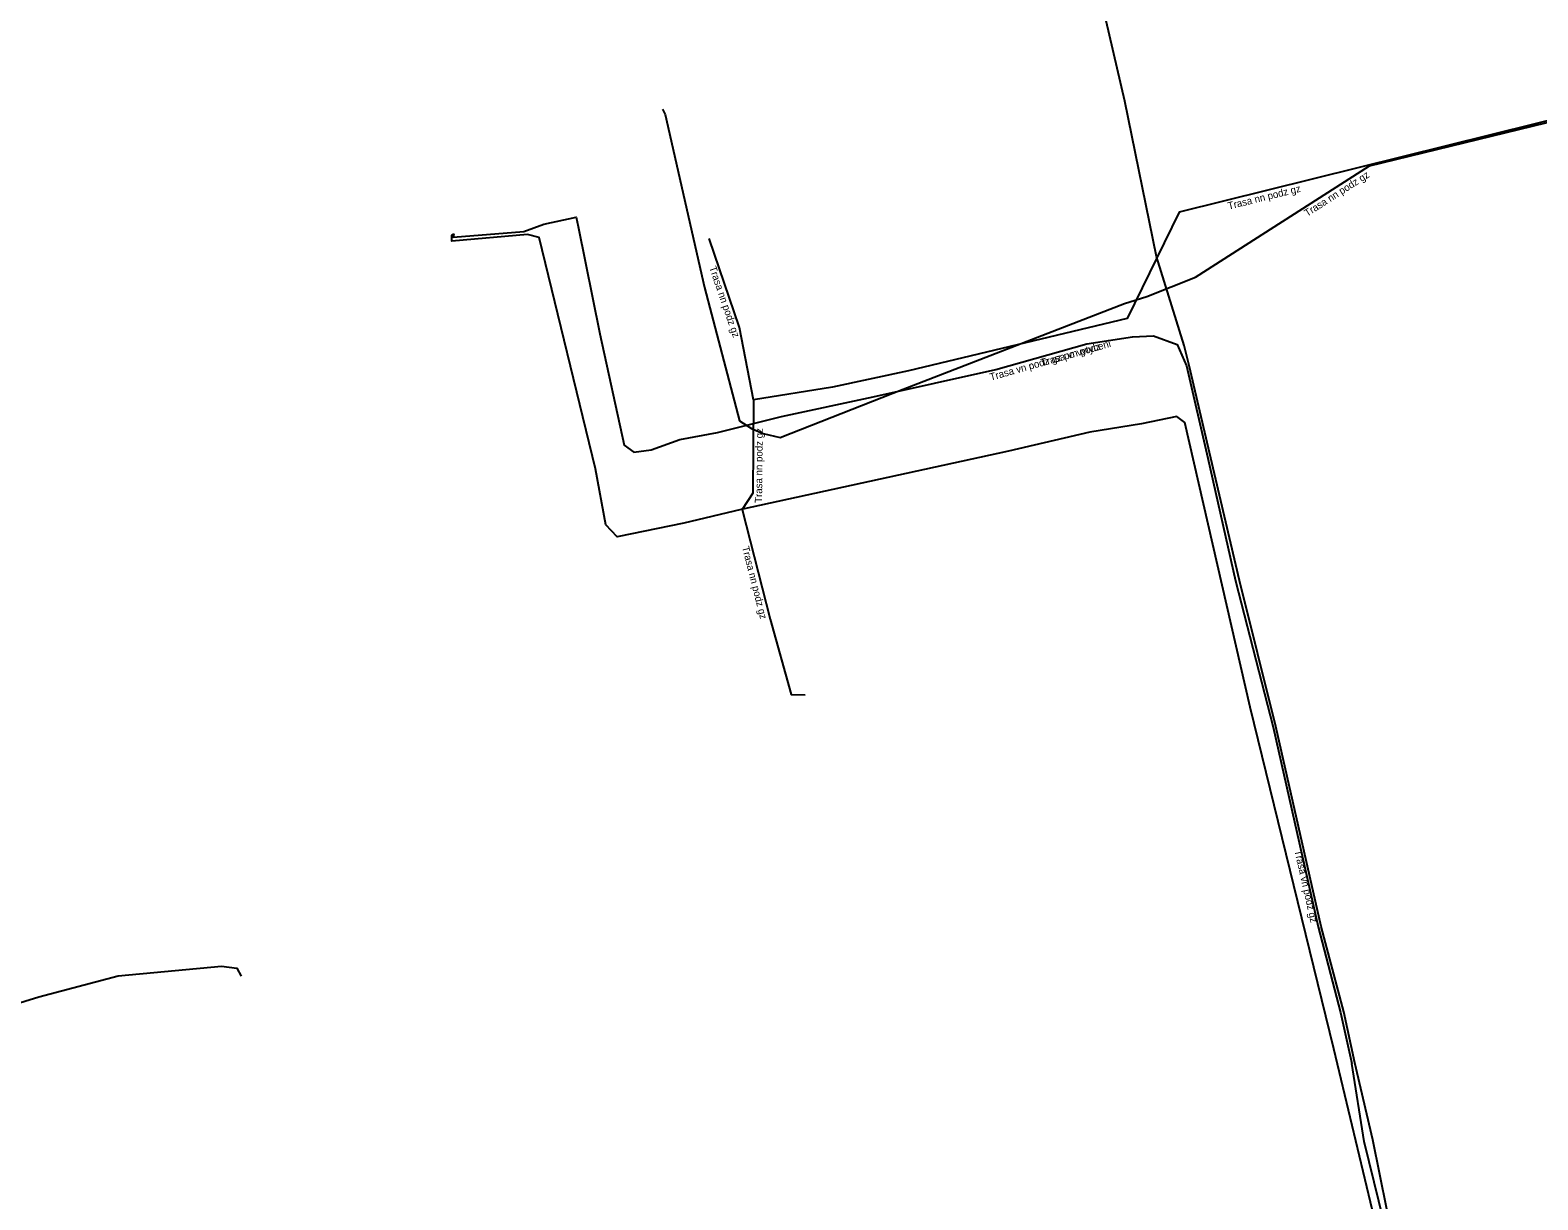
# Model space of a CAD drawing. Extents: x -473082 to -472599, y -1107914 to -1107370.
# Drawn here: x -472981 to -472876.8, y -1107632.7 to -1107551.9 of the extents above; entities that cross this region are included whole.
import ezdxf

# ---------------------------------------------------------------- set-up
doc = ezdxf.new("R2010")
doc.units = 0
for name, color, linetype in [('Popiskový text - Ostatní atributy Trasy', 7, 'Continuous'), ('Spojnice NN', 7, 'Continuous'), ('Spojnice VN', 7, 'Continuous')]:
    doc.layers.add(name, color=color, linetype=linetype)

msp = doc.modelspace()

# ---------------------------------------------------------------- linework, layer by layer
at = {"layer": 'Spojnice NN'}
for points in [[(-472853.99, -1107552.31), (-472861.54, -1107554.54), (-472901.55, -1107564.47), (-472905.15, -1107571.8), (-472913.81, -1107573.89), (-472920.25, -1107575.42), (-472925.51, -1107576.56), (-472930.96, -1107577.42)], [(-472937.26, -1107557.34), (-472937.08, -1107557.71), (-472934.36, -1107569.66), (-472931.94, -1107578.87), (-472931.11, -1107579.4), (-472930.3, -1107579.76), (-472929.13, -1107580.04), (-472921.35, -1107576.98), (-472905.33, -1107570.78), (-472903.79, -1107570.29), (-472900.43, -1107568.96), (-472888.4, -1107561.26), (-472867.72, -1107556.23)], [(-472930.96, -1107577.42), (-472931.93, -1107572.44), (-472934.04, -1107566.29)], [(-472930.96, -1107577.42), (-472931.02, -1107583.88)], [(-472931.02, -1107583.88), (-472931.76, -1107585.01), (-472929.83, -1107592.59), (-472928.36, -1107597.79), (-472927.41, -1107597.8)], [(-472981.13, -1107637.11), (-472982.76, -1107629.43), (-472984.24, -1107619.86), (-472980.36, -1107618.68), (-472974.86, -1107617.23), (-472967.73, -1107616.56), (-472966.66, -1107616.69), (-472966.37, -1107617.24)]]:
    msp.add_lwpolyline(points, dxfattribs=at)
at = {"layer": 'Spojnice VN'}
for points in [[(-472875.95, -1107634.94), (-472882.42, -1107637.24), (-472884.7, -1107637.44), (-472886.06, -1107636.68), (-472886.73, -1107635.73), (-472888.17, -1107628.55), (-472889.42, -1107623.23), (-472890.17, -1107619.72), (-472891.75, -1107613.81), (-472894.87, -1107599.99), (-472897.4, -1107589.9), (-472899.37, -1107581.45), (-472900.86, -1107575.05), (-472901.22, -1107573.68), (-472903.13, -1107567.52), (-472905.32, -1107556.79), (-472907.67, -1107546.67)], [(-472951.68, -1107565.97), (-472951.73, -1107566.19), (-472946.84, -1107565.81), (-472945.46, -1107565.29), (-472943.22, -1107564.81), (-472943.09, -1107565.46), (-472941.6, -1107572.87), (-472939.91, -1107580.56), (-472939.25, -1107581.04), (-472938.05, -1107580.89), (-472936.06, -1107580.17), (-472933.46, -1107579.69), (-472929.03, -1107578.59), (-472922.71, -1107577.22), (-472914.23, -1107575.34), (-472907.93, -1107573.56), (-472904.79, -1107573.07), (-472903.32, -1107573.02), (-472901.69, -1107573.61), (-472901.04, -1107575.09), (-472899.57, -1107581.47), (-472897.66, -1107589.93), (-472895.07, -1107600.05), (-472891.96, -1107613.84), (-472890.4, -1107619.76), (-472889.63, -1107623.29)], [(-472951.68, -1107565.97), (-472951.73, -1107566.19), (-472946.84, -1107565.81), (-472945.46, -1107565.29), (-472943.22, -1107564.81), (-472943.09, -1107565.46), (-472941.6, -1107572.87), (-472939.91, -1107580.56), (-472939.25, -1107581.04), (-472938.05, -1107580.89), (-472936.06, -1107580.17), (-472933.46, -1107579.69), (-472929.03, -1107578.59), (-472922.71, -1107577.22), (-472914.23, -1107575.34), (-472907.93, -1107573.56), (-472904.79, -1107573.07), (-472903.32, -1107573.02), (-472901.69, -1107573.61), (-472901.04, -1107575.09), (-472899.57, -1107581.47), (-472897.66, -1107589.93), (-472895.07, -1107600.05), (-472891.96, -1107613.84), (-472890.4, -1107619.76), (-472889.63, -1107623.29)], [(-472872.74, -1107635.74), (-472879.7, -1107636.72), (-472885.57, -1107637.54), (-472886.75, -1107637.43), (-472887.57, -1107636.03), (-472890.88, -1107622.26), (-472896.66, -1107598.66), (-472901.17, -1107578.99), (-472901.72, -1107578.58), (-472904.16, -1107579.08), (-472907.72, -1107579.66), (-472913.35, -1107580.97), (-472931.82, -1107585.01), (-472935.78, -1107585.94), (-472940.39, -1107586.9), (-472941.18, -1107586.07), (-472941.89, -1107582.19), (-472945.77, -1107566.21), (-472946.59, -1107566.01), (-472951.81, -1107566.48), (-472951.81, -1107566.06), (-472951.68, -1107565.97)], [(-472887.07, -1107635.61), (-472888.78, -1107628.66), (-472889.63, -1107623.29)]]:
    msp.add_lwpolyline(points, dxfattribs=at)

# ---------------------------------------------------------------- texts
at = {"layer": 'Popiskový text - Ostatní atributy Trasy'}
for s, rotation, p in [('Trasa nn podz gz', 32.601, (-472892.71, -1107564.79)), ('Trasa nn podz gz', 13.9385, (-472898.13, -1107564.29)), ('Trasa nn podz gz', 288.9366, (-472934.04, -1107568.29)), ('Trasa vn podz gz po vytyceni', 15.7771, (-472914.57, -1107576.11)), ('Trasa vn podz', 15.7771, (-472911.03, -1107575.11)), ('Trasa nn podz gz', 89.4501, (-472930.38, -1107584.55)), ('Trasa nn podz gz', 284.285, (-472931.77, -1107587.61)), ('Trasa vn podz gz', 282.7218, (-472893.6, -1107608.58))]:
    msp.add_text(s, height=0.5, rotation=rotation, dxfattribs=at).set_placement(p)

doc.saveas('drawing.dxf')
